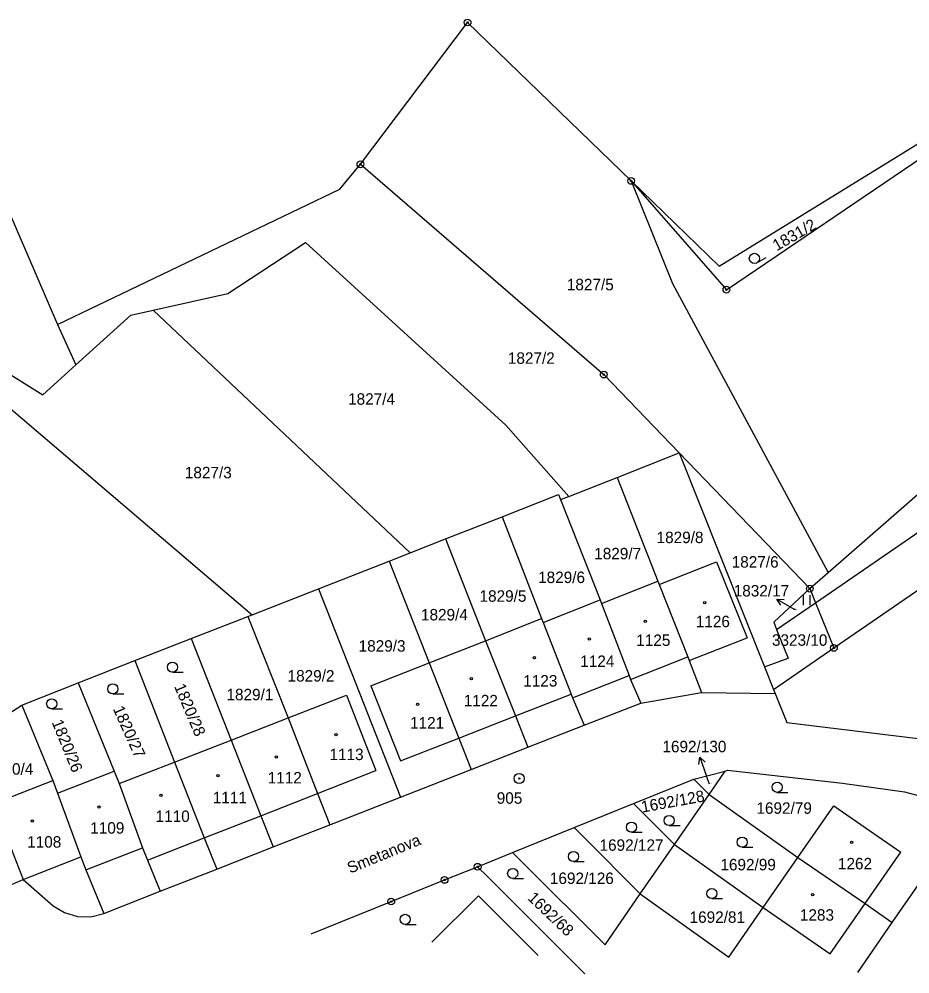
# Model space of a CAD drawing. Extents: x -763205 to -760228, y -1155311 to -1152844.
# Drawn here: x -761740.6 to -761608.6, y -1155158.4 to -1155016.8 of the extents above; entities that cross this region are included whole.
import ezdxf

# ---------------------------------------------------------------- set-up
doc = ezdxf.new("R2010")
doc.units = 0
for name, color, linetype in [('Vrstva 1', 7, 'Continuous'), ('Vrstva 15', 7, 'Continuous'), ('Vrstva 16', 7, 'Continuous'), ('Vrstva 17', 7, 'Continuous'), ('Vrstva 18', 7, 'Continuous'), ('Vrstva 19', 7, 'Continuous'), ('Vrstva 24', 7, 'Continuous'), ('Vrstva 25', 7, 'Continuous'), ('Vrstva 4', 7, 'Continuous')]:
    doc.layers.add(name, color=color, linetype=linetype)

msp = doc.modelspace()

# ---------------------------------------------------------------- linework, layer by layer
at = {"layer": 'Vrstva 1'}
for p, q in [((-761690.05, -1155038.33), (-761674.17, -1155017.3)), ((-761674.17, -1155017.3), (-761649.93, -1155040.79)), ((-761752.85, -1155020.61), (-761734.93, -1155062.1)), ((-761636.9, -1155053.42), (-761604.43, -1155033.44)), ((-761693.09, -1155042.01), (-761690.05, -1155038.33)), ((-761690.05, -1155038.33), (-761653.99, -1155069.51)), ((-761635.81, -1155056.92), (-761606.49, -1155037.08)), ((-761649.93, -1155040.79), (-761636.9, -1155053.42)), ((-761649.93, -1155040.79), (-761643.79, -1155055.98)), ((-761649.93, -1155040.79), (-761635.81, -1155056.92)), ((-761734.93, -1155062.1), (-761693.09, -1155042.01)), ((-761709.7, -1155057.5), (-761698.2, -1155049.9)), ((-761698.2, -1155049.9), (-761668.5, -1155077)), ((-761763.6, -1155056.1), (-761737.1, -1155072.5)), ((-761643.79, -1155055.98), (-761620.74, -1155098.84)), ((-761720.76, -1155059.96), (-761709.7, -1155057.5)), ((-761732.22, -1155068.07), (-761724.1, -1155060.7)), ((-761724.1, -1155060.7), (-761720.76, -1155059.96)), ((-761720.76, -1155059.96), (-761682.67, -1155095.92)), ((-761734.93, -1155062.1), (-761732.22, -1155068.07)), ((-761737.1, -1155072.5), (-761732.22, -1155068.07)), ((-761653.99, -1155069.51), (-761642.82, -1155081.1)), ((-761744.69, -1155072.22), (-761706.11, -1155105.11)), ((-761668.5, -1155077), (-761659.18, -1155087.57)), ((-761652.02, -1155084.76), (-761642.82, -1155081.1)), ((-761642.82, -1155081.1), (-761630.15, -1155112.85)), ((-761642.82, -1155081.1), (-761623.45, -1155101.25)), ((-761659.18, -1155087.57), (-761652.02, -1155084.76)), ((-761652.02, -1155084.76), (-761645.97, -1155100.13)), ((-761622.6, -1155103.34), (-761597.24, -1155085.88)), ((-761620.74, -1155098.84), (-761605.95, -1155085.97)), ((-761669.06, -1155090.59), (-761660.68, -1155087.3)), ((-761660.68, -1155087.3), (-761660.39, -1155088.04)), ((-761660.39, -1155088.04), (-761659.18, -1155087.57)), ((-761660.39, -1155088.04), (-761654.54, -1155102.92)), ((-761677.43, -1155093.87), (-761669.06, -1155090.59)), ((-761669.06, -1155090.59), (-761663.19, -1155105.69)), ((-761619.87, -1155110.04), (-761593.09, -1155091.53)), ((-761682.67, -1155095.92), (-761677.43, -1155093.87)), ((-761677.43, -1155093.87), (-761671.52, -1155108.97)), ((-761685.81, -1155097.15), (-761682.67, -1155095.92)), ((-761696.28, -1155101.26), (-761685.81, -1155097.15)), ((-761685.81, -1155097.15), (-761679.86, -1155112.26)), ((-761645.77, -1155100.64), (-761637.26, -1155097.29)), ((-761637.26, -1155097.29), (-761632.74, -1155108.55)), ((-761623.45, -1155101.25), (-761620.74, -1155098.84)), ((-761654.34, -1155103.43), (-761645.97, -1155100.13)), ((-761645.97, -1155100.13), (-761645.77, -1155100.64)), ((-761645.77, -1155100.64), (-761641.54, -1155111.38)), ((-761706.11, -1155105.11), (-761696.28, -1155101.26)), ((-761696.28, -1155101.26), (-761684.11, -1155132.16)), ((-761628.8, -1155106.21), (-761623.45, -1155101.25)), ((-761623.45, -1155101.25), (-761622.6, -1155103.34)), ((-761662.98, -1155106.25), (-761654.54, -1155102.92)), ((-761654.54, -1155102.92), (-761654.34, -1155103.43)), ((-761654.34, -1155103.43), (-761650.23, -1155114.13)), ((-761628.36, -1155107.31), (-761622.6, -1155103.34)), ((-761622.6, -1155103.34), (-761619.87, -1155110.04)), ((-761715.13, -1155108.64), (-761706.75, -1155105.36)), ((-761706.75, -1155105.36), (-761706.11, -1155105.11)), ((-761706.75, -1155105.36), (-761700.74, -1155120.4)), ((-761671.52, -1155108.97), (-761663.19, -1155105.69)), ((-761663.19, -1155105.69), (-761662.98, -1155106.25)), ((-761662.98, -1155106.25), (-761658.81, -1155116.88)), ((-761628.8, -1155106.21), (-761628.36, -1155107.31)), ((-761628.36, -1155107.31), (-761626.67, -1155111.54)), ((-761723.5, -1155111.92), (-761715.13, -1155108.64)), ((-761715.13, -1155108.64), (-761709.22, -1155123.7)), ((-761679.86, -1155112.26), (-761671.52, -1155108.97)), ((-761671.52, -1155108.97), (-761667.09, -1155120.12)), ((-761641.33, -1155111.92), (-761632.74, -1155108.55)), ((-761628.81, -1155116.22), (-761619.87, -1155110.04)), ((-761731.88, -1155115.2), (-761723.5, -1155111.92)), ((-761723.5, -1155111.92), (-761717.6, -1155126.96)), ((-761641.54, -1155111.38), (-761641.33, -1155111.92)), ((-761641.33, -1155111.92), (-761639.48, -1155116.63)), ((-761630.15, -1155112.85), (-761626.67, -1155111.54)), ((-761688.5, -1155115.67), (-761679.86, -1155112.26)), ((-761679.86, -1155112.26), (-761675.47, -1155123.41)), ((-761630.15, -1155112.85), (-761628.81, -1155116.22)), ((-761650.23, -1155114.13), (-761650, -1155114.7)), ((-761650, -1155114.7), (-761648.51, -1155118.21)), ((-761740.26, -1155118.5), (-761731.88, -1155115.2)), ((-761731.88, -1155115.2), (-761726.55, -1155128.3)), ((-761688.5, -1155115.67), (-761684.11, -1155126.8)), ((-761628.81, -1155116.22), (-761628.58, -1155116.8)), ((-761700.74, -1155120.4), (-761692.12, -1155117.04)), ((-761692.12, -1155117.04), (-761687.77, -1155128.2)), ((-761658.81, -1155116.88), (-761658.6, -1155117.42)), ((-761658.6, -1155117.42), (-761656.89, -1155121.49)), ((-761648.51, -1155118.21), (-761639.48, -1155116.63)), ((-761639.48, -1155116.63), (-761628.58, -1155116.8)), ((-761628.58, -1155116.8), (-761626.86, -1155121.11)), ((-761744.66, -1155121.39), (-761740.26, -1155118.5)), ((-761740.26, -1155118.5), (-761735.64, -1155129.71)), ((-761656.89, -1155121.49), (-761648.51, -1155118.21)), ((-761709.22, -1155123.7), (-761700.74, -1155120.4)), ((-761700.74, -1155120.4), (-761696.42, -1155131.6)), ((-761667.09, -1155120.12), (-761665.26, -1155124.77)), ((-761665.26, -1155124.77), (-761656.89, -1155121.49)), ((-761626.86, -1155121.11), (-761600.56, -1155124.31)), ((-761684.11, -1155126.8), (-761675.47, -1155123.41)), ((-761675.47, -1155123.41), (-761673.64, -1155128.05)), ((-761717.6, -1155126.96), (-761709.22, -1155123.7)), ((-761709.22, -1155123.7), (-761704.83, -1155134.91)), ((-761673.64, -1155128.05), (-761665.26, -1155124.77)), ((-761725.82, -1155130.16), (-761717.6, -1155126.96)), ((-761717.6, -1155126.96), (-761713.2, -1155138.2)), ((-761734.93, -1155131.56), (-761726.55, -1155128.3)), ((-761726.55, -1155128.3), (-761725.82, -1155130.16)), ((-761696.42, -1155131.6), (-761687.77, -1155128.2)), ((-761684.11, -1155132.16), (-761673.64, -1155128.05)), ((-761640.62, -1155129.49), (-761635.99, -1155128.3)), ((-761637.3, -1155130.19), (-761635.99, -1155128.3)), ((-761635.99, -1155128.3), (-761635.63, -1155128.18)), ((-761635.63, -1155128.18), (-761618.61, -1155130.07)), ((-761744.44, -1155133.13), (-761735.64, -1155129.71)), ((-761735.64, -1155129.71), (-761734.93, -1155131.56)), ((-761725.82, -1155130.16), (-761722.36, -1155139.66)), ((-761649.58, -1155133.12), (-761640.62, -1155129.49)), ((-761639.15, -1155130.97), (-761640.62, -1155129.49)), ((-761638.38, -1155131.75), (-761637.3, -1155130.19)), ((-761618.61, -1155130.07), (-761609.4, -1155131.36)), ((-761734.93, -1155131.56), (-761731.49, -1155141.02)), ((-761696.42, -1155131.6), (-761694.58, -1155136.26)), ((-761643.52, -1155139.18), (-761638.38, -1155131.75)), ((-761638.38, -1155131.75), (-761639.15, -1155130.97)), ((-761638.38, -1155131.75), (-761625.2, -1155141.09)), ((-761609.4, -1155131.36), (-761607.41, -1155131.91)), ((-761744.44, -1155133.13), (-761740.05, -1155144.39)), ((-761694.58, -1155136.26), (-761684.11, -1155132.16)), ((-761658.37, -1155136.68), (-761649.58, -1155133.12)), ((-761649.58, -1155133.12), (-761648.12, -1155134.58)), ((-761648.12, -1155134.58), (-761643.52, -1155139.18)), ((-761625.2, -1155141.09), (-761619.9, -1155133.44)), ((-761619.9, -1155133.44), (-761609.97, -1155140.31)), ((-761704.83, -1155134.91), (-761702.96, -1155139.54)), ((-761702.96, -1155139.54), (-761694.58, -1155136.26)), ((-761667.5, -1155140.38), (-761658.37, -1155136.68)), ((-761658.37, -1155136.68), (-761656.89, -1155138.16)), ((-761713.2, -1155138.2), (-761711.34, -1155142.82)), ((-761656.89, -1155138.16), (-761648.57, -1155146.48)), ((-761611.24, -1155150.77), (-761603.09, -1155138.95)), ((-761722.36, -1155139.66), (-761721.63, -1155141.52)), ((-761711.34, -1155142.82), (-761702.96, -1155139.54)), ((-761672.68, -1155142.48), (-761667.5, -1155140.38)), ((-761667.5, -1155140.38), (-761666.02, -1155141.85)), ((-761648.57, -1155146.48), (-761643.52, -1155139.18)), ((-761643.52, -1155139.18), (-761630.36, -1155148.53)), ((-761615.26, -1155147.94), (-761609.97, -1155140.31)), ((-761731.49, -1155141.02), (-761730.73, -1155142.95)), ((-761721.63, -1155141.52), (-761719.71, -1155146.1)), ((-761630.36, -1155148.53), (-761625.2, -1155141.09)), ((-761625.2, -1155141.09), (-761615.26, -1155147.94)), ((-761730.73, -1155142.95), (-761728.1, -1155149.42)), ((-761719.71, -1155146.1), (-761711.34, -1155142.82)), ((-761677.58, -1155144.44), (-761672.68, -1155142.48)), ((-761672.68, -1155142.48), (-761671.22, -1155143.95)), ((-761666.02, -1155141.85), (-761653.8, -1155154.04)), ((-761742.8, -1155145.55), (-761740.05, -1155144.39)), ((-761740.05, -1155144.39), (-761735.58, -1155148.27)), ((-761685.48, -1155147.64), (-761677.58, -1155144.44)), ((-761671.22, -1155143.95), (-761656.79, -1155158.37)), ((-761728.1, -1155149.42), (-761719.71, -1155146.1)), ((-761672.57, -1155146.81), (-761679.47, -1155153.65)), ((-761663.72, -1155155.64), (-761672.57, -1155146.81)), ((-761653.8, -1155154.04), (-761648.57, -1155146.48)), ((-761648.57, -1155146.48), (-761635.45, -1155155.88)), ((-761735.58, -1155148.27), (-761733.89, -1155149.29)), ((-761697.37, -1155152.45), (-761685.48, -1155147.64)), ((-761635.45, -1155155.88), (-761630.36, -1155148.53)), ((-761630.36, -1155148.53), (-761620.42, -1155155.38)), ((-761615.26, -1155147.94), (-761611.24, -1155150.77)), ((-761733.89, -1155149.29), (-761731.98, -1155149.86)), ((-761731.98, -1155149.86), (-761730.03, -1155149.91)), ((-761730.03, -1155149.91), (-761728.1, -1155149.42)), ((-761616.34, -1155158.17), (-761611.24, -1155150.77))]:
    msp.add_line(p, q, dxfattribs=at)
at = {"layer": 'Vrstva 16'}
for p, q in [((-761628.355, -1155102.784), (-761625.76, -1155104.29)), ((-761625.58, -1155104.39), (-761625.76, -1155104.29)), ((-761639.753, -1155126.223), (-761638.75, -1155129.05)), ((-761638.33, -1155130.22), (-761638.75, -1155129.05))]:
    msp.add_line(p, q, dxfattribs=at)
for points in [[(-761627.741, -1155103.719), (-761628.355, -1155102.784), (-761627.239, -1155102.854)], [(-761639.89, -1155127.332), (-761639.753, -1155126.223), (-761638.948, -1155126.998)]]:
    msp.add_lwpolyline(points, dxfattribs=at)
at = {"layer": 'Vrstva 24'}
for centre, radius in [((-761674.17, -1155017.3), 0.5), ((-761674.17, -1155017.3), 0.1), ((-761690.05, -1155038.33), 0.5), ((-761690.05, -1155038.33), 0.1), ((-761649.93, -1155040.79), 0.5), ((-761649.93, -1155040.79), 0.1), ((-761635.81, -1155056.92), 0.5), ((-761635.81, -1155056.92), 0.1), ((-761653.99, -1155069.51), 0.5), ((-761653.99, -1155069.51), 0.1), ((-761623.45, -1155101.25), 0.5), ((-761623.45, -1155101.25), 0.1), ((-761619.87, -1155110.04), 0.5), ((-761619.87, -1155110.04), 0.1), ((-761666.52, -1155129.4), 0.75), ((-761666.52, -1155129.4), 0.1), ((-761672.68, -1155142.48), 0.5), ((-761672.68, -1155142.48), 0.1), ((-761677.58, -1155144.44), 0.5), ((-761677.58, -1155144.44), 0.1), ((-761685.48, -1155147.64), 0.5), ((-761685.48, -1155147.64), 0.1)]:
    msp.add_circle(centre, radius, dxfattribs=at)
at = {"layer": 'Vrstva 25'}
for p, q in [((-761631.29, -1155052.93), (-761629.901, -1155052.135)), ((-761624.37, -1155103.72), (-761624.37, -1155102.22)), ((-761623.37, -1155103.72), (-761623.37, -1155102.22)), ((-761717.92, -1155113.65), (-761716.32, -1155113.65)), ((-761726.74, -1155116.86), (-761725.14, -1155116.86)), ((-761735.81, -1155119.08), (-761734.21, -1155119.08)), ((-761628.28, -1155131.45), (-761626.68, -1155131.45)), ((-761649.88, -1155137.37), (-761648.28, -1155137.37)), ((-761644.28, -1155136.38), (-761642.68, -1155136.38)), ((-761633.47, -1155139.59), (-761631.87, -1155139.59)), ((-761658.48, -1155141.72), (-761656.88, -1155141.72)), ((-761667.48, -1155144.22), (-761665.88, -1155144.22)), ((-761637.97, -1155147.21), (-761636.37, -1155147.21)), ((-761683.41, -1155151.03), (-761681.81, -1155151.03))]:
    msp.add_line(p, q, dxfattribs=at)
for centre, radius in [((-761631.663, -1155052.279), 0.75), ((-761639.01, -1155103.34), 0.175), ((-761647.83, -1155106.11), 0.175), ((-761656.13, -1155108.7), 0.175), ((-761664.27, -1155111.47), 0.175), ((-761717.92, -1155112.9), 0.75), ((-761673.61, -1155114.59), 0.175), ((-761726.74, -1155116.11), 0.75), ((-761735.81, -1155118.33), 0.75), ((-761681.57, -1155118.4), 0.175), ((-761693.68, -1155122.9), 0.175), ((-761702.5, -1155126.19), 0.175), ((-761711.15, -1155128.96), 0.175), ((-761628.28, -1155130.7), 0.75), ((-761719.63, -1155131.91), 0.175), ((-761728.8, -1155133.64), 0.175), ((-761738.66, -1155135.71), 0.175), ((-761649.88, -1155136.62), 0.75), ((-761644.28, -1155135.63), 0.75), ((-761633.47, -1155138.84), 0.75), ((-761617.26, -1155138.88), 0.175), ((-761658.48, -1155140.97), 0.75), ((-761667.48, -1155143.47), 0.75), ((-761637.97, -1155146.46), 0.75), ((-761623.03, -1155146.63), 0.175), ((-761683.41, -1155150.28), 0.75)]:
    msp.add_circle(centre, radius, dxfattribs=at)
at = {"layer": 'Vrstva 4'}
for p, q in [((-761650, -1155114.7), (-761641.54, -1155111.38)), ((-761658.6, -1155117.42), (-761650.23, -1155114.13)), ((-761667.09, -1155120.12), (-761658.81, -1155116.88)), ((-761675.47, -1155123.41), (-761667.09, -1155120.12)), ((-761704.83, -1155134.91), (-761696.42, -1155131.6)), ((-761713.2, -1155138.2), (-761704.83, -1155134.91)), ((-761721.63, -1155141.52), (-761713.2, -1155138.2)), ((-761730.73, -1155142.95), (-761722.36, -1155139.66)), ((-761740.05, -1155144.39), (-761731.49, -1155141.02)), ((-761620.42, -1155155.38), (-761615.26, -1155147.94))]:
    msp.add_line(p, q, dxfattribs=at)

# ---------------------------------------------------------------- texts
at = {"layer": 'Vrstva 15'}
msp.add_text('Smetanova', height=1.7, rotation=22.34535, dxfattribs=at).set_placement((-761691.58, -1155143.52))
at = {"layer": 'Vrstva 16'}
for s, p in [('1832/17', (-761634.723, -1155102.41)), ('1692/130', (-761645.292, -1155125.51))]:
    msp.add_text(s, height=1.7, dxfattribs=at).set_placement(p)
at = {"layer": 'Vrstva 17'}
msp.add_text('905', height=1.7, dxfattribs=at).set_placement((-761669.848, -1155133.14))
at = {"layer": 'Vrstva 18'}
for s, rotation, p in [('1831/2', 29.79381, (-761628.349, -1155051.235)), ('1820/28', 292.83873, (-761717.688, -1155115.742)), ('1820/27', 294.21383, (-761726.769, -1155119.068)), ('1820/26', 292.26577, (-761735.831, -1155121.053)), ('1692/128', 10.25594, (-761648.273, -1155134.465)), ('1692/68', 316.44459, (-761665.385, -1155147.251))]:
    msp.add_text(s, height=1.7, rotation=rotation, dxfattribs=at).set_placement(p)
for s, height, p in [('1827/5', 1.7, (-761659.457, -1155057.01)), ('1827/2', 1.7, (-761668.197, -1155067.91)), ('1827/4', 1.7, (-761691.877, -1155073.98)), ('1827/3', 1.7, (-761716.077, -1155084.89)), ('1829/8', 1.7, (-761646.157, -1155094.5)), ('1829/7', 1.7, (-761655.397, -1155096.9)), ('1827/6', 1.7, (-761635.027, -1155098.13)), ('1829/6', 1.7, (-761663.717, -1155100.42)), ('1829/5', 1.7, (-761672.397, -1155103.19)), ('1829/4', 1.7, (-761681.077, -1155105.96)), ('1832/17', 0.1, (-761625.831, -1155104.39)), ('1829/3', 1.7, (-761690.317, -1155110.59)), ('3323/10', 1.7, (-761629.055, -1155109.72)), ('1829/2', 1.7, (-761700.847, -1155115.02)), ('1829/1', 1.7, (-761709.907, -1155117.8)), ('1820/4', 1.7, (-761745.482, -1155128.83)), ('1692/130', 0.1, (-761638.624, -1155130.22)), ('1692/79', 1.7, (-761631.357, -1155134.63)), ('1692/127', 1.7, (-761654.612, -1155140.12)), ('1692/99', 1.7, (-761636.697, -1155143.02)), ('1692/126', 1.7, (-761661.972, -1155145.04)), ('1692/81', 1.7, (-761641.267, -1155150.8))]:
    msp.add_text(s, height=height, dxfattribs=at).set_placement(p)
at = {"layer": 'Vrstva 19'}
for s, p in [('1126', (-761640.347, -1155106.97)), ('1125', (-761649.167, -1155109.74)), ('1124', (-761657.467, -1155112.86)), ('1123', (-761665.917, -1155115.76)), ('1122', (-761674.737, -1155118.7)), ('1121', (-761682.697, -1155121.99)), ('1113', (-761694.637, -1155126.67)), ('1112', (-761703.797, -1155130.13)), ('1111', (-761711.937, -1155133.07)), ('1110', (-761720.407, -1155135.84)), ('1109', (-761730.097, -1155137.58)), ('1108', (-761739.447, -1155139.65)), ('1262', (-761619.277, -1155142.87)), ('1283', (-761624.917, -1155150.48))]:
    msp.add_text(s, height=1.7, dxfattribs=at).set_placement(p)

doc.saveas('drawing.dxf')
